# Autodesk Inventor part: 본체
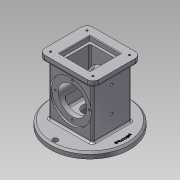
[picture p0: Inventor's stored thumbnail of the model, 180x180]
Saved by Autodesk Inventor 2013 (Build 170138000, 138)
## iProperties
Created: 2019-08
Part Number: 본체
Material: 알루미늄 6061
Document SubType Name: Modeling
Designer: hana-cad17
Density: 2.40731 g/cm^3
Mass: 926.847 g
Surface Area: 782.841 cm^2
Volume: 385.013 cm^3
Author: hana-cad17
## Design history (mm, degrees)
sketch "스케치1"
  geometry: C1 r 67.5 at (0, 0); 1 further point
  constraints: 1 centre point, 1 coincident
  dimensions: "d0" = 135 diameter of C1
extrude "돌출1" new body sketch "스케치1" distance "d1" = 10; taper "d2" = 0 deg
sketch "스케치2"
  geometry: L1 (-37, 33)-(37, 33); L2 (37, 33)-(37, -33); L3 (37, -33)-(-37, -33); L4 (-37, -33)-(-37, 33); L5 (-37, 33)-(37, -33); L6 (37, 33)-(-37, -33); C1 r 67.5 at (0, 0) reference; 2 further points
  constraints: 12 end point, 3 midpoint, 2 parallel, 1 coincident, 1 horizontal, 1 perpendicular
  dimensions: "d3" = 74 distance of L1.start L1.end; "d5" = 66 distance of L1.end L2.end
extrude "돌출2" join sketch "스케치2" distance "d6" = 98; taper "d7" = 0 deg
sketch "스케치3"
  geometry: L1 (37, 33)-(-37, 33) reference; L2 (-37, 33)-(-37, -33) reference; L3 (-37, -33)-(37, -33) reference; L4 (37, -33)-(37, 33) reference; L5 (-46, 41)-(46, 41); L6 (46, 41)-(46, -41); L7 (46, -41)-(-46, -41); L8 (-46, -41)-(-46, 41); L9 (-46, 41)-(46, -41); L10 (46, 41)-(-46, -41); 2 further points
  constraints: 12 end point, 4 midpoint, 2 parallel, 1 horizontal, 1 perpendicular
  dimensions: "d8" = 92 distance of L5.start L5.end; "d10" = 82 distance of L5.end L6.end
extrude "돌출3" join sketch "스케치3" distance "d11" = 10; taper "d12" = 0 deg
fillet "모깎기1" dims "d13" = 10
hole "구멍1" diameter "d16" = 3.242; stored, may be unused: countersink angle "d20" = 90 deg, drill point angle "d22" = 118 deg; dims "d14" = 10, "d15" = 10, "d17" = 4, "d18" = 4, "d19" = 2, "d21" = 6
sketch "스케치5"
  geometry: L1 (-26, 26)-(26, 26); L2 (26, 26)-(26, -26); L3 (26, -26)-(-26, -26); L4 (-26, -26)-(-26, 26); L5 (-26, 26)-(26, -26); L6 (26, 26)-(-26, -26); 3 further points
  constraints: 12 end point, 3 midpoint, 2 parallel, 2 perpendicular, 1 coincident, 1 horizontal
  dimensions: "d29" = 52 distance of L1.start L1.end
extrude "돌출4" cut sketch "스케치5" distance "d31" = 8; taper "d32" = 0 deg
sketch "스케치6"
  geometry: L1 (-22, 22)-(22, 22); L2 (22, 22)-(22, -22); L3 (22, -22)-(-22, -22); L4 (-22, -22)-(-22, 22); L5 (-22, 22)-(22, -22); L6 (22, 22)-(-22, -22); 3 further points
  constraints: 12 end point, 3 midpoint, 2 parallel, 2 perpendicular, 1 coincident, 1 horizontal
  dimensions: "d33" = 44 distance of L1.start L1.end
extrude "돌출5" cut sketch "스케치6" distance "d35" = 74; taper "d36" = 0 deg
sketch "스케치7"
  geometry: C1 r 67.5 at (0, 0) reference; C2 r 25 at (0, 0)
  constraints: 1 centre point, 1 coincident
  dimensions: "d37" = 50 diameter of C2
extrude "돌출6" cut sketch "스케치7" distance "d39" = 18; taper "d40" = 0 deg
sketch "스케치8"
  geometry: C1 r 25 at (0, 0) reference; C2 r 12.5 at (0, 0)
  constraints: 1 centre point, 1 coincident
  dimensions: "d41" = 25 diameter of C2
extrude "돌출7" cut sketch "스케치8" stored distance "d43" = 18; taper "d44" = 0 deg
sketch "스케치9"
  geometry: L1 (-30.5, -10)-(104.5, -10) reference; L2 (73, 88)-(1, 88) reference; C1 r 35 at (37, 44); 2 further points
  constraints: 1 centre point, 1 midpoint, 1 vertical alignment
  dimensions: "d45" = 54 distance from line of L1 C1.centre; "d46" = 70 diameter of C1
extrude "돌출8" cut sketch "스케치9" distance "d47" = 3; taper "d48" = 0 deg
sketch "스케치10"
  geometry: C1 r 35 at (0, 0) reference; C2 r 24 at (0, 0); 1 further point
  constraints: 1 centre point, 1 coincident
  dimensions: "d49" = 48 diameter of C2
extrude "돌출9" cut sketch "스케치10" stored distance "d51" = 3; taper "d52" = 0 deg
sketch "스케치11"
  geometry: C1 r 25 at (0, 0) reference; 3 further points
  constraints: 2 vertical alignment, 1 horizontal alignment
  dimensions: "d53" = 59 distance of C1.centre point (0, 59); "d84" = 59 distance of point (0, -59) C1.centre; "d85" = 59 distance of point (-59, 0) C1.centre
hole "구멍2" sketch "스케치11" at (0, 59), (0, -59), (-59, 0) diameter "d54" = 9; stored, may be unused: countersink angle "d58" = 90 deg, drill point angle "d60" = 118 deg; dims "d55" = 4, "d56" = 4, "d57" = 2, "d59" = 6
sketch "스케치12"
  geometry: C1 r 24 at (0, 0) reference; 2 further points
  constraints: 1 vertical alignment
  dimensions: "d64" = 29 distance of C1.centre point (0, 29)
hole "구멍3" sketch "스케치12" at (0, 29) diameter "d65" = 3.242; stored, may be unused: countersink angle "d69" = 90 deg, drill point angle "d71" = 118 deg; dims "d66" = 4, "d67" = 4, "d68" = 2, "d70" = 6
sketch "스케치13"
  geometry: L1 (-10, 100.5)-(-10, -34.5) reference; 3 further points
  constraints: 2 horizontal alignment
  dimensions: "d75" = 37 distance from line of L1 point (27, 33); "d76" = 43 distance of point (70, 33) point (27, 33)
hole "구멍4" sketch "스케치13" at (27, 33), (70, 33) diameter "d77" = 4.917; stored, may be unused: countersink angle "d81" = 90 deg, drill point angle "d83" = 118 deg; dims "d78" = 20, "d79" = 4, "d80" = 2, "d82" = 6
node "작업 평면1"
sketch "스케치14"
  geometry: C1 r 59 at (0, 0); 1 further point
  constraints: 1 centre point, 1 coincident, 1 other
  dimensions: "d87" = 118 diameter of C1
feature "엠보싱1" sketch "스케치14" dims "d88" = 0.5, "d89" = 0
chamfer "모따기1" distance "d90" = 3; stored, may be unused: second distance "d91" = 2, angle "d92" = 45 deg
fillet "모깎기2" dims "d93" = 3
fillet "모깎기3" dims "d94" = 3
chamfer "모따기2" distance "d95" = 1; stored, may be unused: second distance "d96" = 2, angle "d97" = 45 deg
fillet "모깎기4" dims "d98" = 3
fillet "모깎기5" dims "d99" = 3
fillet "모깎기6" dims "d100" = 3
fillet "모깎기7" dims "d101" = 3
node "솔리드1"
pattern_linear "직사각형 패턴1" dims "d25" = 72, "d28" = 62
mirror "대칭1"
pattern_circular "원형 패턴2" dims angle "d73" = 360 deg
mirror "대칭2"
